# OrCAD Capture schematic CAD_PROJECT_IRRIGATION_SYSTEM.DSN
size A; title: Circuit for controlling soil moisture level for plants; rev: 1; note: 1
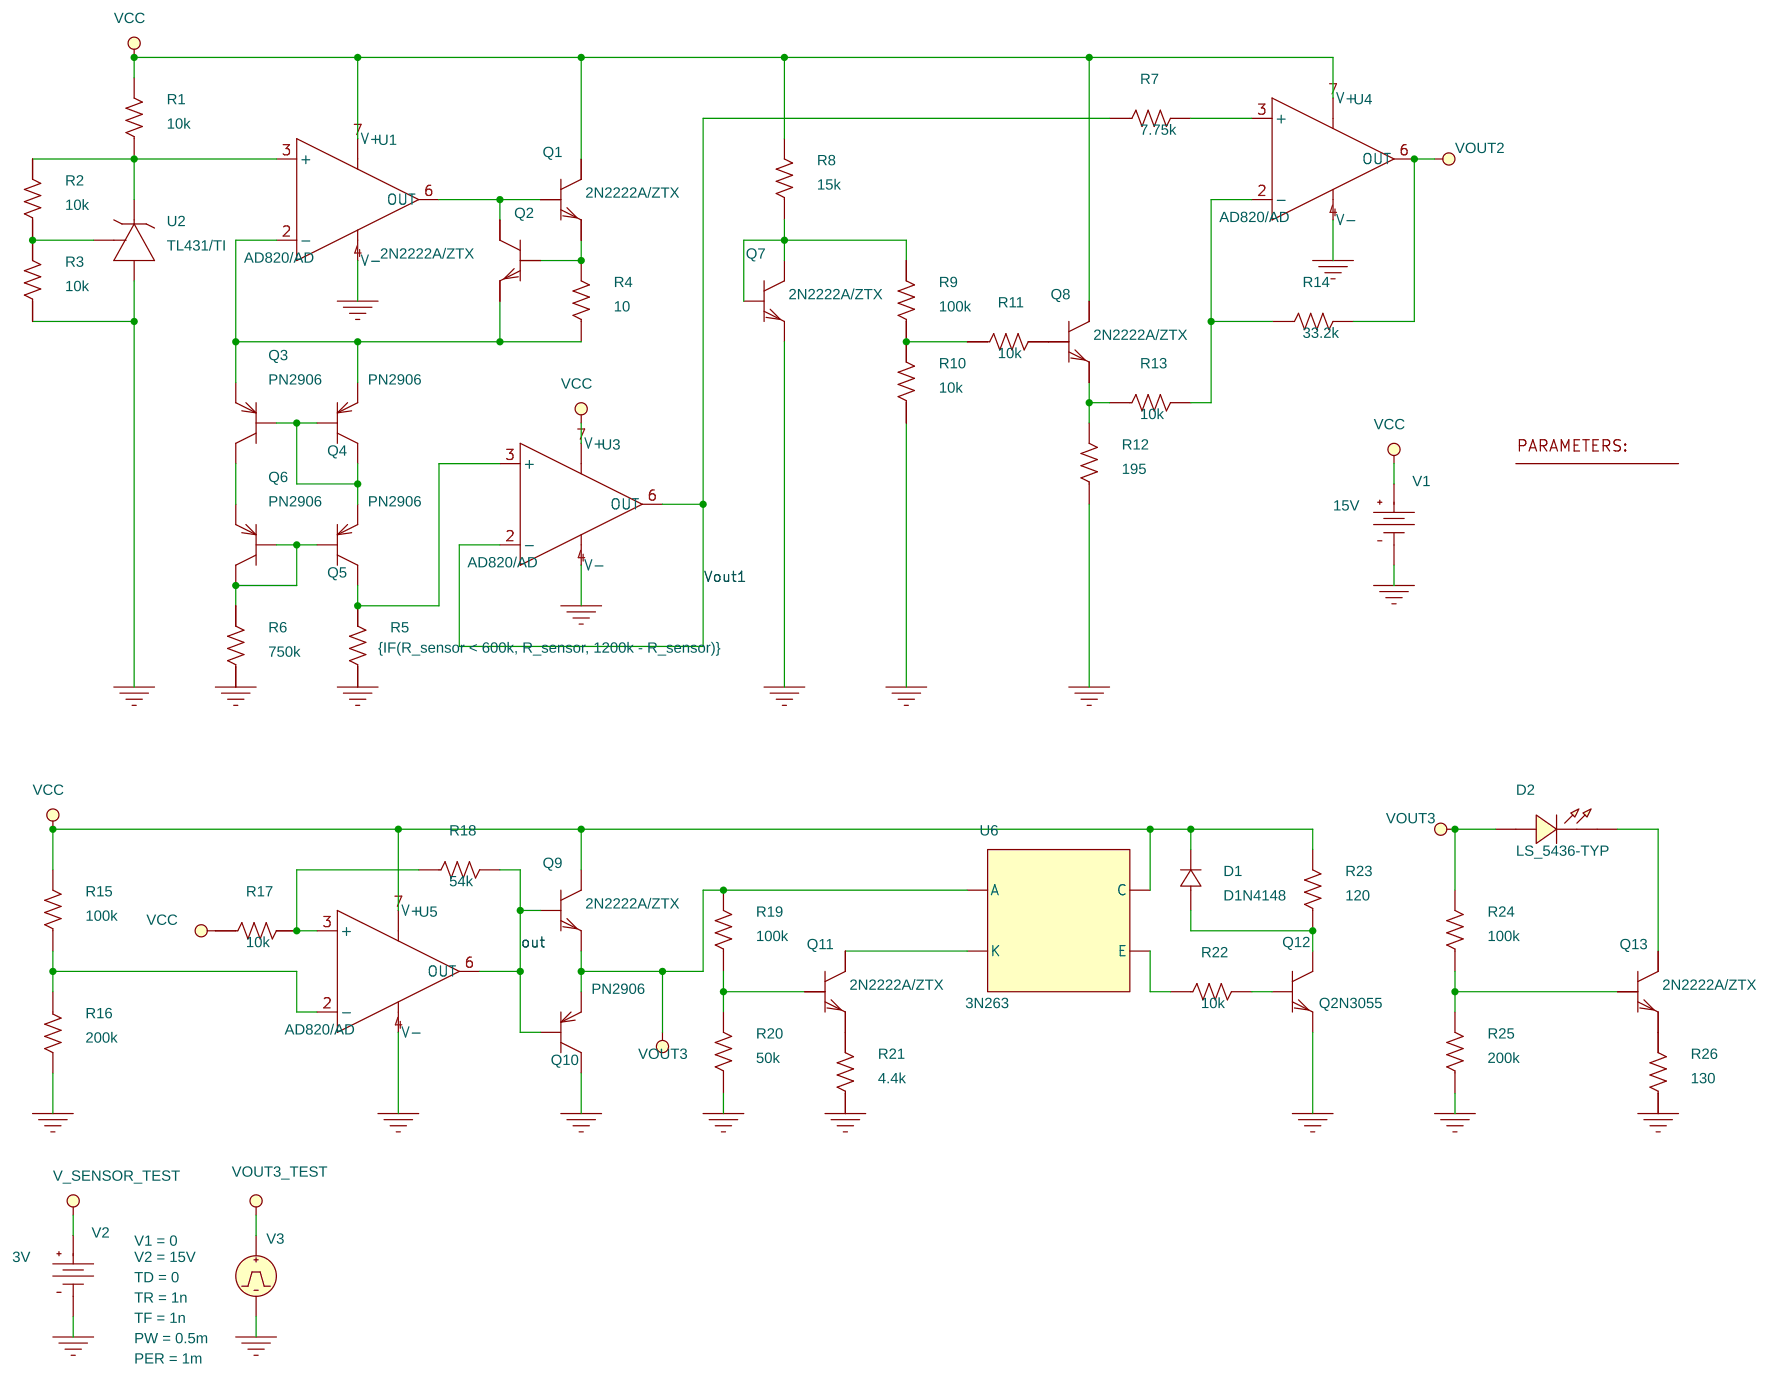
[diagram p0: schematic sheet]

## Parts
1  PARAM
D1  D1N4148  [dax2do35]
D2  LS_5436-TYP
Q1  2N2222A/ZTX  [TO18]
Q2  2N2222A/ZTX  [TO18]
Q3  PN2906  [to92]
Q4  PN2906  [to92]
Q5  PN2906  [to92]
Q6  PN2906  [to92]
Q7  2N2222A/ZTX  [TO18]
Q8  2N2222A/ZTX  [TO18]
Q9  2N2222A/ZTX  [TO18]
Q10  PN2906  [to92]
Q11  2N2222A/ZTX  [TO18]
Q12  Q2N3055  [TO204]
Q13  2N2222A/ZTX  [TO18]
R1  10k  [AXRC05]
R2  10k  [AXRC05]
R3  10k  [AXRC05]
R4  10  [AXRC05]
R5  {IF(R_sensor < 600k, R_sensor, 1200k - R_sensor)}  [AXRC05]
R6  750k  [AXRC05]
R7  7.75k  [AXRC05]
R8  15k  [AXRC05]
R9  100k  [AXRC05]
R10  10k  [AXRC05]
R11  10k  [AXRC05]
R12  195  [AXRC05]
R13  10k  [AXRC05]
R14  33.2k  [AXRC05]
R15  100k  [AXRC05]
R16  200k  [AXRC05]
R17  10k  [AXRC05]
R18  54k  [AXRC05]
R19  100k  [AXRC05]
R20  50k  [AXRC05]
R21  4.4k  [AXRC05]
R22  10k  [AXRC05]
R23  120  [AXRC05]
R24  100k  [AXRC05]
R25  200k  [AXRC05]
R26  130  [AXRC05]
U1  AD820/AD  [DIP1008W300L450]
U2  TL431/TI
U3  AD820/AD  [DIP1008W300L450]
U4  AD820/AD  [DIP1008W300L450]
U5  AD820/AD  [DIP1008W300L450]
U6  3N263  [to17r050]
V1  VDC
V2  VDC
V3  VPULSE

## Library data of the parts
1 = PARAM: R_protection: 100; R_protetion: 1k; R_sensor: 410k
D1 = 1N4148
D2 = LS_5436-TYP
Q1 Q2 Q7-Q9 Q11 Q13 = 2N2222A_ZTX
Q3-Q6 Q10 = PN2906
Q12 = Q2N3055
R1-R4 R6-R22 R24-R26 = R: TOLERANCE: 1
R5 R23 = R
U1 U3-U5 = AD820_AD
U2 = TL431_TI
U6 = 3N263
V1 = VDC: DC: 15V
V2 = VDC: DC: 3V
V3 = VPULSE: PER: 1m; PW: 0.5m; TD: 0; TF: 1n; TR: 1n; V1: 0; V2: 15V

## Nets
VCC: D1.2 Q1.3(C) Q8.3(C) Q9.3(C) R1.2 R8.2 R15.2 R23.2 U1.7(V+) U3.7(V+) U4.7(V+) U5.7(V+) U6.C V1.0(+)
0: Q7.1(E) Q10.3(c) Q12.2(e) R3.1 R5.1 R6.1 R10.1 R12.1 R16.2 R20.1 R21.1 R25.1 R26.1 U1.4(V-) U2.2(AN) U3.4(V-) U4.4(V-) U5.4(V-) V1.1(-) V2.1(-) V3.2(-)
out: Q9.2(B) Q10.2(b) R18.2 U5.6(OUT)
V_sensor_test: V2.0(+)
Vout1: R7.1 U3.2(-) U3.6(OUT)
Vout2: R14.2 R17.1 U4.6(OUT)
Vout3: D2.1 Q9.1(E) Q10.1(e) R19.2 R24.2 U6.A
Vout3_test: V3.1(+)
N00408: Q1.2(B) Q2.3(C) U1.6(OUT)
N00498: Q1.1(E) Q2.2(B) R4.2
N00507: Q2.1(E) Q3.1(e) Q4.1(e) R4.1 U1.2(-)
N00563: R1.1 R2.2 U1.3(+) U2.3(CAT)
N00618: R2.1 R3.2 U2.1(REF)
N01894: Q3.2(b) Q4.2(b) Q4.3(c) Q5.1(e)
N01898: Q3.3(c) Q6.1(e)
N01906: Q5.2(b) Q6.2(b) Q6.3(c) R6.2
N02218: Q5.3(c) R5.2 U3.3(+)
N06042: Q7.2(B) Q7.3(C) R8.1 R9.2
N06051: R9.1 R10.2 R11.1
N06628: R13.2 R14.1 U4.2(-)
N06831: R7.2 U4.3(+)
N07043: Q8.1(E) R12.2 R13.1
N10669: R15.1 R16.1 U5.2(-)
N10780: R17.2 R18.1 U5.3(+)
N16378: Q11.2(B) R19.1 R20.2
N16540: Q11.3(C) U6.K
N16711: R22.1 U6.E
N16722: Q12.1(b) R22.2
N17266: D1.1 Q12.3(c) R23.1
N53563: Q13.2(B) R24.1 R25.2
N53806: D2.2 Q13.3(C)
N63479: Q13.1(E) R26.2
N63480: Q8.2(B) R11.2
N63481: Q11.1(E) R21.2
